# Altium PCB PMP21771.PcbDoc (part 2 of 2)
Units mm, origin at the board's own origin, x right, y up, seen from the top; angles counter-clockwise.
Board outline 125.73 x 87.63 mm, 4 copper layers (Top Layer, Signal Layer 1, Signal Layer 2, Bottom Layer), stack 2.225 mm thick; 58 components, 23 nets, 122 pads, 58 vias.
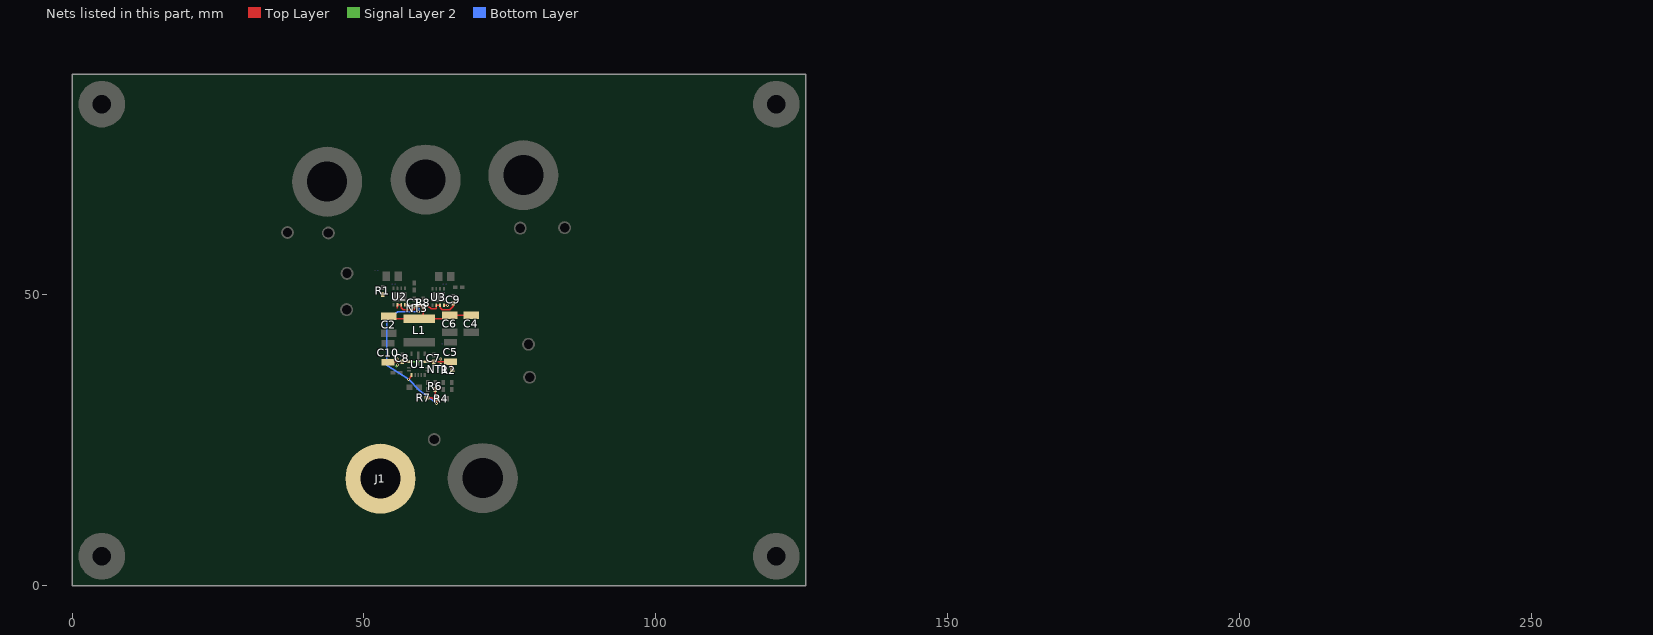
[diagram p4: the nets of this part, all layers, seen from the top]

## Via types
v1: diameter 0.508, hole 0.203, Top Layer to Bottom Layer, 50 vias
v2: diameter 0.5, hole 0.2, Top Layer to Bottom Layer, 8 vias

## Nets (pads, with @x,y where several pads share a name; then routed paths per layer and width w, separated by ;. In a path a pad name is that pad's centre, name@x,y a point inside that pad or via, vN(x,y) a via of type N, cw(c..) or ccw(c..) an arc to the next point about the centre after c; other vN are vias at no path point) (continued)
VIN: C5.1 C7.1 C8.1 C10.1 J1.1 NT1.2 R2.2 U1.8 U1.12 | length 23
  Top Layer w0.254: J1.1@52.702,18.498 J1.1@52.825,18.375 ; C10.1@54.126,38.3 54.226,38.4 C8.1@56.576,38.4 57.821,38.4 U1.12@57.836,38.415 ; U1.8@61.135,38.415 U1.8@60.736,38.415 60.746,38.425 C5.1@64.826,38.425 ; R2.2@65.1,36.925 C5.1@64.826,38.425 ; C5.1@65.1,38.151 C5.1@64.826,38.425
  Signal Layer 2 w0.254: J1.1@52.825,18.375 J1.1@55.75,21.3 ; 55.439,37.572 v1(55.75,37.883) ; 55.825,38.4 63.175,38.4
  Bottom Layer w0.254: NT1.2@62.715,37.4 62.715,37.49 v1(63.15,37.925)
  other v1: 55.775,38.85 63.15,38.85
VIN2: C1.1 C2.1 C4.1 C6.1 C9.1 L1.2 NT3.1 R1.2 R4.2 R6.2 R7.2 R8.2 U1.1 U2.2 U2.3 U2.4 U3.2 U3.3 U3.4 | length 62.5
  Top Layer w0.254: R1.2@53.134,50.2 R1.2@53.23,50.104 ; C2.1@54.25,46.174 54.627,45.797 L1.2@59.476,45.797 ; 55.721,47.571 U2.2@55.721,48.171 U2.3@56.371,48.171 56.371,47.671 56.737,47.305 58.598,47.305 C1.1@58.598,47.955 R8.2@60.18,47.955 ; U2.4@57.021,48.171 v1(57.7,48.171) ; v1(57.65,35.4) 58.136,35.886 U1.1@58.136,36.115 ; R7.2@60.8,32.232 61.575,32.232 61.745,32.062 R4.2@62.443,32.062 ; R6.2@62.24,33.65 62.24,32.265 R4.2@62.443,32.062 ; v1(62.443,31.275) R4.2@62.443,32.062 ; U3.4@63.69,48.1 64.275,48.1 v1(64.3,48.075) ; C9.1@65.33,48.421 65.33,47.906 64.702,47.278 63.392,47.278 63.04,47.63 U3.3@63.04,48.1 U3.2@62.39,48.1 62.368,48.078 62.368,47.575 62.268,47.475 61.998,47.475 61.996,47.473 61.483,47.473 61.002,47.955 R8.2@60.18,47.955 ; C4.1@68.395,46.378 C6.1@64.702,46.378 64.121,45.797 L1.2@59.476,45.797 ; L1.2@59.476,45.797 60.18,46.501 R8.2@60.18,47.955
  Bottom Layer w0.254: NT3.1@59.4,47.575 59.4,47.025 v1(59.35,46.975) 55.79,46.975 55.752,47.012 53.86,45.71 53.86,37.765 v1(57.65,35.4) 59.485,33.565 v1(62.443,31.275)
pads on no net: H1.1 H2.1 H3.1 H4.1 H5.0 H6.0 H7.0 H8.0 U1.10@59.286,38.315 U1.10@59.286,39.615 U2.9@55.416,49.571 U2.9@56.676,49.571 U3.9@62.085,49.5 U3.9@63.345,49.5
copper on no net: | length 2642.9
  Signal Layer 1 w0.025: 236.74,55.732 239.272,58.264 242.32,61.312 245.368,64.36 248.416,67.408 251.464,70.456 254.512,73.504 257.56,76.552 260.608,79.6 263.656,82.648 265.18,84.172 ; 236.74,57.256 237.748,58.264 240.796,61.312 243.844,64.36 246.892,67.408 249.94,70.456 252.988,73.504 256.036,76.552 259.084,79.6 262.132,82.648 265.18,85.696 ; 236.74,58.78 239.272,61.312 242.32,64.36 245.368,67.408 248.416,70.456 251.464,73.504 254.512,76.552 257.56,79.6 260.608,82.648 263.656,85.696 265.18,87.22 ; 236.74,60.304 237.748,61.312 240.796,64.36 243.844,67.408 246.892,70.456 249.94,73.504 252.988,76.552 256.036,79.6 259.084,82.648 262.132,85.696 265.18,88.744 ; 236.74,61.828 239.272,64.36 242.32,67.408 245.368,70.456 248.416,73.504 251.464,76.552 254.512,79.6 257.56,82.648 260.608,85.696 263.656,88.744 ; 236.74,63.352 237.748,64.36 240.796,67.408 243.844,70.456 246.892,73.504 249.94,76.552 252.988,79.6 256.036,82.648 259.084,85.696 262.132,88.744 ; 236.74,64.876 239.272,67.408 242.32,70.456 245.368,73.504 248.416,76.552 251.464,79.6 254.512,82.648 257.56,85.696 260.608,88.744 ; 236.74,66.4 237.748,67.408 240.796,70.456 243.844,73.504 246.892,76.552 249.94,79.6 252.988,82.648 256.036,85.696 259.084,88.744 ; 236.74,67.924 239.272,70.456 242.32,73.504 245.368,76.552 248.416,79.6 251.464,82.648 254.512,85.696 257.56,88.744 ; 236.74,69.448 237.748,70.456 240.796,73.504 243.844,76.552 246.892,79.6 249.94,82.648 252.988,85.696 256.036,88.744 ; 236.74,70.972 239.272,73.504 242.32,76.552 245.368,79.6 248.416,82.648 251.464,85.696 254.512,88.744 ; 236.74,72.496 237.748,73.504 240.796,76.552 243.844,79.6 246.892,82.648 249.94,85.696 252.988,88.744 ; 236.74,74.02 239.272,76.552 242.32,79.6 245.368,82.648 248.416,85.696 251.464,88.744 ; 236.74,75.544 237.748,76.552 240.796,79.6 243.844,82.648 246.892,85.696 249.94,88.744 ; 236.74,77.068 239.272,79.6 242.32,82.648 245.368,85.696 248.416,88.744 ; 236.74,78.592 237.748,79.6 240.796,82.648 243.844,85.696 246.892,88.744 ; 236.74,80.116 239.272,82.648 242.32,85.696 245.368,88.744 ; 236.74,81.64 237.748,82.648 240.796,85.696 243.844,88.744 ; 236.74,83.164 239.272,85.696 242.32,88.744 ; 236.74,84.688 237.748,85.696 240.796,88.744 ; 236.74,86.212 239.272,88.744 ; 236.74,87.736 237.748,88.744 ; 237.748,55.216 240.796,58.264 243.844,61.312 246.892,64.36 249.94,67.408 252.988,70.456 256.036,73.504 259.084,76.552 262.132,79.6 265.18,82.648 ; 239.272,55.216 242.32,58.264 245.368,61.312 248.416,64.36 251.464,67.408 254.512,70.456 257.56,73.504 260.608,76.552 263.656,79.6 265.18,81.124 ; 240.796,55.216 243.844,58.264 246.892,61.312 249.94,64.36 252.988,67.408 256.036,70.456 259.084,73.504 262.132,76.552 265.18,79.6 ; 242.32,55.216 245.368,58.264 248.416,61.312 251.464,64.36 254.512,67.408 257.56,70.456 260.608,73.504 263.656,76.552 265.18,78.076 ; 243.844,55.216 246.892,58.264 249.94,61.312 252.988,64.36 256.036,67.408 259.084,70.456 262.132,73.504 265.18,76.552 ; 245.368,55.216 248.416,58.264 251.464,61.312 254.512,64.36 257.56,67.408 260.608,70.456 263.656,73.504 265.18,75.028 ; 246.892,55.216 249.94,58.264 252.988,61.312 256.036,64.36 259.084,67.408 262.132,70.456 265.18,73.504 ; 248.416,55.216 251.464,58.264 254.512,61.312 257.56,64.36 260.608,67.408 263.656,70.456 265.18,71.98 ; 249.94,55.216 252.988,58.264 256.036,61.312 259.084,64.36 262.132,67.408 265.18,70.456 ; 251.464,55.216 254.512,58.264 257.56,61.312 260.608,64.36 263.656,67.408 265.18,68.932 ; 252.988,55.216 256.036,58.264 259.084,61.312 262.132,64.36 265.18,67.408 ; 254.512,55.216 257.56,58.264 260.608,61.312 263.656,64.36 265.18,65.884 ; 256.036,55.216 259.084,58.264 262.132,61.312 265.18,64.36 ; 257.56,55.216 260.608,58.264 263.656,61.312 265.18,62.836 ; 259.084,55.216 262.132,58.264 265.18,61.312 ; 260.608,55.216 263.656,58.264 265.18,59.788 ; 262.132,55.216 265.18,58.264 ; 263.656,55.216 265.18,56.74
  Signal Layer 1 w0.381: 149.641,58.264 160.052,58.264 183.922,58.264 205.76,58.264 222.266,58.264 236.74,58.264 265.18,58.264 ; 149.641,61.312 160.052,61.312 183.922,61.312 205.76,61.312 222.266,61.312 236.74,61.312 265.18,61.312 ; 149.641,64.36 160.052,64.36 183.922,64.36 205.76,64.36 222.266,64.36 236.74,64.36 265.18,64.36 ; 149.641,67.408 160.052,67.408 183.922,67.408 205.76,67.408 222.266,67.408 236.74,67.408 265.18,67.408 ; 149.641,70.456 160.052,70.456 183.922,70.456 205.76,70.456 222.266,70.456 236.74,70.456 265.18,70.456 ; 149.641,73.504 160.052,73.504 183.922,73.504 205.76,73.504 222.266,73.504 236.74,73.504 265.18,73.504 ; 149.641,76.552 160.052,76.552 183.922,76.552 205.76,76.552 222.266,76.552 236.74,76.552 265.18,76.552 ; 149.641,79.6 160.052,79.6 183.922,79.6 205.76,79.6 222.266,79.6 236.74,79.6 265.18,79.6 ; 149.641,82.648 160.052,82.648 183.922,82.648 205.76,82.648 222.266,82.648 236.74,82.648 265.18,82.648 ; 149.641,85.696 160.052,85.696 183.922,85.696 205.76,85.696 222.266,85.696 236.74,85.696 265.18,85.696 ; 149.641,88.744 265.18,88.744 ; 160.052,91.792 160.052,55.216 ; 183.922,91.792 183.922,55.216 ; 205.76,91.792 205.76,55.216 ; 222.266,91.792 222.266,55.216 ; 236.74,91.792 236.74,55.216 ; 160.052,55.216 149.641,55.216 149.641,91.792 265.18,91.792 265.18,55.216 236.74,55.216 ; 160.052,55.216 183.922,55.216 ; 183.922,55.216 205.76,55.216 ; 205.76,55.216 222.266,55.216 ; 222.266,55.216 236.74,55.216

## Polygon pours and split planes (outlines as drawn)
GND on Signal Layer 1 "SIGNAL_LAYER_1_GND_P152" (solid, remove dead copper, pour order 152): 126.05,87.63 125.603,87.183 125.603,-0.127 0.127,-0.127 0,0 0.325,0.325 0.325,87.63
OUT2 on Top Layer "TOP_LAYER_OUT2_P144" (solid, remove dead copper, pour order 144): 69.856,77.925 83.15,77.925 89.717,71.358 64.74,46.38 61.585,51.418
OUT1 on Top Layer "TOP_LAYER_OUT1_P145" (solid, remove dead copper, pour order 145): 36.526,76.525 47.573,76.525 55.082,63.955 56.791,50.994 50.514,50.661 35.977,65.198
GND on Top Layer "TOP_LAYER_GND_P150" (solid, remove dead copper, pour order 150): -0.713,87.783 125.312,87.783 125.312,0.194 125.017,-0.101 124.763,0.153 -0.713,0.153
VIN on Top Layer "TOP_LAYER_VIN_P149" (solid, remove dead copper, pour order 149): 60.236,39.125 60.35,39.24 66.226,39.24 66.226,36.474 60.259,36.474
VIN on Top Layer "TOP_LAYER_VIN_P147" (solid, remove dead copper, pour order 147): 52.726,39.115 58.5,39.115 58.5,37.4 52.726,37.4
GND on Top Layer "TOP_LAYER_GND_P146" (solid, remove dead copper, pour order 146): 64.1,54 67.1,54 67.1,52.05 67.125,52.025 64.075,52.025
OUT2 on Top Layer "TOP_LAYER_OUT2_P143" (solid, remove dead copper, pour order 143): 61.996,54 63.589,54 63.589,50.483 63.575,50.469 63.544,50.5 61.986,50.5
OUT1 on Top Layer "TOP_LAYER_OUT1_P142" (solid, remove dead copper, pour order 142): 54.975,54.225 55.025,54.275 56.725,54.275 56.725,50.6 56.65,50.525 56.6,50.575 54.996,50.575
SW on Top Layer "TOP_LAYER_SW_P141" (solid, remove dead copper, pour order 141): 56.55,42.65 62.4,42.65 62.289,40.675 59.85,40.648 59.85,37.6 58.95,37.6 58.8,37.75 58.8,40.325 58.45,40.675 56.55,40.675
VIN2 on Top Layer "TOP_LAYER_VIN2_P140" (solid, remove dead copper, pour order 140): 51.7,50.85 51.85,51 70.275,51 70.275,44.75 51.7,44.75
VIN on Signal Layer 2 "SIGNAL_LAYER_2_VIN_P151" (solid, remove dead copper, pour order 151): 53.25,37.977 45.025,29.752 45.025,11.425 60.269,11.425 60.269,37.814
GND on Signal Layer 2 "SIGNAL_LAYER_2_GND_P153" (solid, remove dead copper, pour order 153): 0,87.63 125.156,87.63 125.603,87.183 125.25,86.83 125.25,0 0.1,0
VIN on Signal Layer 2 "SIGNAL_LAYER_2_VIN_P148" (solid, remove dead copper, pour order 148): 52.561,39.115 52.786,39.34 66.486,39.34 66.486,36.225 66.461,36.2 66.421,36.24 64.082,36.24 64.082,36.499 63.292,37.29 63.217,37.215 52.561,37.215
GND on Bottom Layer "BOTTOM_LAYER_GND_P154" (solid, remove dead copper, pour order 154): 0,87.35 0.167,87.183 125.603,87.183 125.603,0.447 126.05,0 0.15,0

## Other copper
Signal Layer 1:
  text "Layer" at 151.165,89.506 h1.52
  text "Name" at 161.576,89.506 h1.52
  text "Material" at 185.446,89.506 h1.52
  text "Thickness" at 207.284,89.506 h1.52
  text "Constant" at 223.79,89.506 h1.52
  text "Board Layer Stack" at 238.264,89.506 h1.52
  text "1" at 151.165,86.458 h1.52
  text "Top Overlay" at 161.576,86.458 h1.52
  text "2" at 151.165,83.41 h1.52
  text "Top Solder" at 161.576,83.41 h1.52
  text "Solder Resist" at 185.446,83.41 h1.52
  text "0.40mil" at 207.284,83.41 h1.52
  text "3.5" at 223.79,83.41 h1.52
  text "3" at 151.165,80.362 h1.52
  text "Top Layer" at 161.576,80.362 h1.52
  text "Copper" at 185.446,80.362 h1.52
  text "2.80mil" at 207.284,80.362 h1.52
  text "4" at 151.165,77.314 h1.52
  text "Dielectric 2" at 161.576,77.314 h1.52
  text "10.00mil" at 207.284,77.314 h1.52
  text "4.2" at 223.79,77.314 h1.52
  text "5" at 151.165,74.266 h1.52
  text "Signal Layer 1" at 161.576,74.266 h1.52
  text "Copper" at 185.446,74.266 h1.52
  text "1.40mil" at 207.284,74.266 h1.52
  text "6" at 151.165,71.218 h1.52
  text "Dielectric1" at 161.576,71.218 h1.52
  text "FR-4" at 185.446,71.218 h1.52
  text "59.20mil" at 207.284,71.218 h1.52
  text "4.8" at 223.79,71.218 h1.52
  text "7" at 151.165,68.17 h1.52
  text "Signal Layer 2" at 161.576,68.17 h1.52
  text "Copper" at 185.446,68.17 h1.52
  text "1.40mil" at 207.284,68.17 h1.52
  text "8" at 151.165,65.122 h1.52
  text "Dielectric 3" at 161.576,65.122 h1.52
  text "10.00mil" at 207.284,65.122 h1.52
  text "4.2" at 223.79,65.122 h1.52
  text "9" at 151.165,62.074 h1.52
  text "Bottom Layer" at 161.576,62.074 h1.52
  text "Copper" at 185.446,62.074 h1.52
  text "2.80mil" at 207.284,62.074 h1.52
  text "10" at 151.165,59.026 h1.52
  text "Bottom Solder" at 161.576,59.026 h1.52
  text "Solder Resist" at 185.446,59.026 h1.52
  text "0.40mil" at 207.284,59.026 h1.52
  text "3.5" at 223.79,59.026 h1.52
  text "11" at 151.165,55.978 h1.52
  text "Bottom Overlay" at 161.576,55.978 h1.52

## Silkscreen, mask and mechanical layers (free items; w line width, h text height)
Top Overlay:
  lines w0.1: 51.1,30.6 51.1,36.625 51.1,48.675 51.1,54.7 70.825,54.7 70.775,30.6 51.1,30.6
M1 Board Outline:
  lines w0.254: 0,0 0,87.63 136.5,87.63 136.5,0 0,0
M2 Board Dimensions:
  rectangle: 0,-6.985 3.175,-3.81
  rectangle: 3.175,-10.16 12.7,-6.985
  lines w0.178: 0,-6.985 25.4,-6.985 ; 3.175,-10.16 3.175,-3.81 ; 6.35,-10.16 6.35,-3.81 ; 12.7,-10.16 12.7,-3.81 ; 19.05,-10.16 19.05,-3.81 ; 0,-10.16 25.4,-10.16 25.4,-3.81 0,-3.81 0,-10.16
M5 Assembly Top:
  lines w0.254: -7.417,-23.626 160.223,-23.626 ; -7.417,-18.462 160.274,-18.462 ; -7.417,-13.297 -7.417,-28.791 94.31,-28.791 160.274,-28.791 160.274,-13.297 -7.404,-13.297 -7.404,-28.791 32.614,-28.791 ; 55.194,-28.791 55.194,-13.297 ; 87.376,-18.462 87.376,-13.297 ; 108.712,-18.462 108.712,-13.297 ; 124.511,-28.956 124.511,-23.804
  text "REV:" at 92.405,-16.654 h1.52
  text ".PCB_Rev" at 99.809,-16.654 h1.52
  text "SVN REV:" at 113.69,-16.654 h1.52
  text ".VersionControl_RevNumber" at 126.543,-16.654 h1.52
  text "TID #:" at 57.099,-21.819 h1.52
  text ".TID" at 70.955,-21.819 h1.52
  text "PLOT NAME =" at -5.804,-27.034 h1.52
  text ".Print_Date" at 79.235,-27.034 h1.52
  text "TEXAS INSTRUMENTS" at 129.87,-27.034 h1.52
M6 Assembly Bottom:
  lines w0.254: -7.429,-18.474 160.261,-18.474 ; -7.379,-23.639 160.261,-23.639 ; 28.334,-28.969 28.334,-23.817 ; 44.133,-18.474 44.133,-13.31 ; 65.468,-18.474 65.468,-13.31 ; 97.65,-28.804 97.65,-13.31 ; 120.231,-28.804 160.249,-28.804 160.249,-13.31 -7.429,-13.31 -7.429,-28.804 58.534,-28.804 160.261,-28.804 160.261,-13.31
  text ".VersionControl_RevNumber" at 26.302,-16.667 h1.52
M9 Title Sheet:
  drawing of 57 lines, arcs and shapes, not listed
  text "1" at 18.792,204.127 h1.78
  text "2" at 82.182,204.127 h1.78
  text "3" at 145.411,204.127 h1.78
  text "4" at 209.08,204.127 h1.78
  text "5" at 272.555,204.127 h1.78
  text "6" at 336.182,204.127 h1.78
  text "A" at -10.579,175.095 h1.78
  text "A" at 365.341,175.095 h1.78
  text "B" at -10.579,114.643 h1.78
  text "B" at 365.341,114.643 h1.78
  text "C" at -10.579,54.318 h1.78
  text "C" at 365.341,54.318 h1.78
  text "PROJECT TITLE:" at 288.125,7.048 h1.14
  text "Dual Type-C Charge Port" at 289.395,3.662 h1.78
  text "DESIGNED FOR:" at 288.125,-0.597 h1.14
  text "Aptiv" at 289.395,-4.153 h1.78
  text "D" at 365.341,-5.88 h1.78
  text "FILE NAME:" at 288.125,-8.217 h1.14
  text ".PCB_File_Name_No_Path" at 289.395,-11.265 h1.78
  text "Texas Instruments (TI) and/or its licensors do not warrant the accuracy or completeness of this specification" at 161.9,-15.376 h1.14
  text "ENGINEER:" at 288.125,-15.583 h1.14
  text "LAYOUT BY:" at 326.352,-15.583 h1.14
  text "or any information contained therein. TI and/or its licensors do not warrant that this design will meet" at 160.757,-18.237 h1.14
  text "PMP21771" at 289.395,-19.52 h1.78
  text "Sahana Krishnan" at 327.635,-19.52 h1.78
  text "the specifications, will be suitable for your application or fit for any particular purpose, or will operate in" at 160.757,-21.099 h1.14
  text "ALTIUM DESIGNER VERSION:" at 326.352,-23.457 h1.14
  text "an implementation. TI and/or its licensors do not warrant that the design is production worthy. You should" at 160.757,-23.961 h1.14
  text "completely validate and test your design implementation to confirm the system functionality for your application." at 161.9,-26.822 h1.14
  text ".print_Scale" at 289.395,-26.843 h1.78
  text ".Application_BuildNumber" at 327.635,-26.843 h1.78
  text "1" at 18.792,-32.093 h1.78
  text "2" at 82.182,-32.093 h1.78
  text "3" at 145.411,-32.093 h1.78
  text "4" at 209.08,-32.093 h1.78
  text "5" at 272.555,-32.093 h1.78
  text "6" at 336.182,-32.093 h1.78
M10 Fab Notes:
  drawing of 189 lines, arcs and shapes, not listed
  text "DESIGN INFORMATION" at 314.503,161.447 h1.52
  text "MIN. TRACK WIDTH:" at 298.131,158.091 h1.52
  text "8" at 325.976,158.091 h1.52
  text "MIL" at 329.907,158.091 h1.52
  text "MIN. CLEARANCE:" at 298.131,154.938 h1.52
  text "0.2" at 324.452,154.938 h1.52
  text "mm" at 329.907,154.938 h1.52
  text "MIN. VIA PAD SIZE:" at 298.131,151.785 h1.52
  text "24" at 325.214,151.785 h1.52
  text "MIL" at 329.907,151.785 h1.52
  text "0.05mm (2MIL)" at 315.784,148.486 h1.52
  text "MINIMUM ANNULAR RING" at 289.769,148.277 h1.52
  text "EXTERNAL" at 333.768,148.277 h1.52
  text "PER" at 294.849,145.48 h1.52
  text "IPC-D-275 CLASS 2 LEVEL C" at 300.437,145.48 h1.52
  text "MIL, HOLES" at 338.238,142.928 h1.52
  text "+/-" at 328.27,142.709 h1.52
  text "+/-" at 349.961,142.709 h1.52
  text "REGISTRATION TOLERANCES:" at 289.769,142.682 h1.52
  text "METAL" at 320.243,142.682 h1.52
  text "5" at 334.879,142.683 h1.52
  text "3" at 356.037,142.683 h1.52
  text "MIL" at 358.99,142.682 h1.52
  text "HOLE SIZE TOLERANCE (UNLESS OTHERWISE SPECIFIED):" at 289.769,140.185 h1.52
  text "+/-" at 349.961,140.112 h1.52
  text "3" at 356.037,140.085 h1.52
  text "MIL" at 358.99,140.085 h1.52
  text "MATERIAL:" at 287.87,136.589 h1.52
  text "FR-4 High Tg" at 312.926,133.324 h1.52
  text "X" at 309.257,133.122 h1.52
  text "FR-408" at 298.563,133.007 h1.52
  text "OTHER" at 336.358,133.007 h1.52
  text "62 MIL (1.6mm) +/-10%" at 306.694,129.374 h1.52
  text "X" at 303.643,129.312 h1.52
  text "THICKNESS:" at 289.769,129.165 h1.52
  text "OTHER" at 339.33,129.165 h1.52
  text "TOLERANCE:" at 289.769,125.652 h1.52
  text "X" at 311.314,125.652 h1.52
  text "ANSI IPC-6012 TYPE 3 CLASS 2" at 315.836,125.652 h1.52
  text "OTHER +/-" at 315.835,121.989 h1.52
  text "BOW & TWIST:" at 289.769,118.302 h1.52
  text "X" at 311.314,118.302 h1.52
  text "ANSI IPC-6012 TYPE 3 CLASS 2" at 315.836,118.302 h1.52
  text "OTHER +/-" at 315.835,114.576 h1.52
  text "DRILLING:" at 287.87,111.258 h1.52
  text "NC_DRILL FILES" at 332.599,108.586 h1.52
  text "REFERENCE:" at 289.769,108.486 h1.52
  text "X" at 306.463,108.484 h1.52
  text "AS SHOWN" at 310.984,108.486 h1.52
  text "X" at 329.348,108.486 h1.52
  text "OTHER" at 340.168,104.873 h1.52
  text "PTH COPPER THICKNESS:" at 289.761,104.783 h1.52
  text "X" at 318.697,104.783 h1.52
  text "20-30 um" at 321.948,104.783 h1.52
  text "BOARD FINISH:" at 287.87,101.034 h1.52
  text "SILKSCREEN:" at 291.812,98.237 h1.52
  text "X" at 316.14,98.237 h1.52
  text "TOP" at 319.112,98.237 h1.52
  text "X" at 329.094,98.237 h1.52
  text "BOTTOM" at 332.091,98.237 h1.52
  text "SILKSCREEN COLOR:" at 291.812,94.295 h1.52
  text "X" at 316.115,94.295 h1.52
  text "WHITE" at 319.112,94.295 h1.52
  text "OTHER" at 332.091,94.295 h1.52
  text "X" at 319.442,90.652 h1.52
  text "GREEN" at 322.439,90.652 h1.52
  text "OTHER" at 338.136,90.652 h1.52
  text "SOLDER RESIST COLOR:" at 291.812,90.477 h1.52
  text "X" at 319.442,86.734 h1.52
  text "MATTE" at 322.439,86.734 h1.52
  text "SEMI-GLOSS" at 338.125,86.717 h1.52
  text "IMMERSION GOLD (ENIG)" at 314.819,82.345 h1.52
  text "ENEPIG" at 348.793,82.162 h1.52
  text "SURFACE FINISH:" at 287.87,82.136 h1.52
  text "X" at 310.298,82.136 h1.52
  text "IMM. TIN/SILVER OR EQUIV" at 296.24,78.649 h1.52
  text "OTHER" at 332.599,78.549 h1.52
  text "ARRAY/PANEL:" at 287.87,74.602 h1.52
  text "CUT AND TRIM PER M1 BOARD OUTLINE" at 314.819,74.393 h1.52
  text "N.C. ROUTE" at 314.819,70.94 h1.52
  text "X" at 332.295,70.94 h1.52
  text "V. SCORE" at 336.816,70.94 h1.52
  text "CERTIFICATION:" at 287.87,67.66 h1.52
  text "MATERIALS AND WORKMANSHIP FOR ALL PCBS" at 306.285,67.66 h1.52
  text "TO MEET OR EXCEED THE REQUIREMENTS OF:" at 306.285,65.271 h1.52
  text "X" at 297.078,62.003 h1.52
  text "ANSI IPC-A-600F CLASS ->" at 300.329,62.003 h1.52
  text "X" at 342.188,62.003 h1.52
  text "2" at 344.982,62.003 h1.52
  text "1" at 336.981,61.965 h1.52
  text "3" at 353.973,61.965 h1.52
  text "X" at 317.702,58.252 h1.52
  text "RoHS" at 320.953,58.252 h1.52
  text "OTHER" at 337.321,58.252 h1.52
  text "PER ORDER" at 347.407,58.252 h1.52
  text "ALL BOARDS MUST MEET OR EXCEED UL94-V0 REQUIREMENTS." at 288.569,54.345 h1.52
  text "PCB MUST BEAR THE UL94V-0 UL REGISTERED MATERIAL ID NUMBER" at 288.569,51.397 h1.52
  text "ADDITIONAL REQUIREMENTS:" at 287.87,47.094 h1.52
  text "MICROSECTION:" at 289.769,44.373 h1.52
  text "YES" at 312.775,44.373 h1.52
  text "REQUIRED" at 334.657,40.707 h1.52
  text "BARE BOARD ELEC. TEST:" at 289.769,40.634 h1.52
  text "NONE" at 322.935,40.634 h1.52
  text "X" at 331.66,40.634 h1.52
  text "PER ORDER" at 349.693,40.634 h1.52
  text "XX MIL VIAS REQUIRE NON-CONDUCTIVE FILL AND PLANARIZE" at 294.04,35.428 h1.5
  text "XX MIL VIAS REQUIRE CONDUCTIVE FILL AND PLANARIZE" at 294.243,32.787 h1.52
  text "OUTER XX MIL TRACES REQUIRE 50 OHM SINGLE-ENDED IMPEDANCE" at 294.218,28.637 h1.47
  text "LAYER 2 & 3 (INNER LAYERS) XX MIL WIDE, XX MIL SPACE / TRACES REQUIRE 100 OHM DIFFERENTIAL IMPEDANCE" at 294.015,22.65 h1.52
M11 Gerber Information:
  lines w0.254: -7.417,-23.626 160.223,-23.626 ; -7.417,-18.462 160.274,-18.462 ; -7.417,-13.297 -7.417,-28.791 94.31,-28.791 160.274,-28.791 160.274,-13.297 -7.404,-13.297 -7.404,-28.791 32.614,-28.791 ; 55.194,-28.791 55.194,-13.297 ; 87.376,-18.462 87.376,-13.297 ; 108.712,-18.462 108.712,-13.297 ; 124.511,-28.956 124.511,-23.804
  text "BOARD #:" at 57.099,-16.654 h1.52
  text "PMP21771" at 70.955,-16.654 h1.52
  text "REV:" at 92.405,-16.654 h1.52
  text ".PCB_Rev" at 99.809,-16.654 h1.52
  text "SVN REV:" at 113.69,-16.654 h1.52
  text ".VersionControl_RevNumber" at 126.543,-16.654 h1.52
  text "LAYER NAME =" at -5.804,-21.806 h1.52
  text "TID #:" at 57.099,-21.819 h1.52
  text ".TID" at 70.955,-21.819 h1.52
  text "PLOT NAME =" at -5.804,-27.034 h1.52
  text "GENERATED    :" at 57.15,-27.034 h1.52
  text ".Print_Date" at 79.235,-27.034 h1.52
  text ".Print_Time" at 97.752,-27.034 h1.52
  text "TEXAS INSTRUMENTS" at 129.87,-27.034 h1.52
Drill Drawing:
  circle w0.254: c161.226,33.627 r0.702
  lines w0.254: 160.525,30.119 160.876,30.119 161.226,29.768 161.577,30.119 161.928,30.119 161.577,30.469 161.928,30.82 161.577,30.82 161.226,31.171 160.876,30.82 160.525,30.82 160.876,30.469 160.525,30.119 ; 160.525,36.083 161.226,36.434 161.928,36.083 161.577,36.785 161.928,37.487 161.226,37.136 160.525,37.487 160.876,36.785 160.525,36.083 ; 160.525,40.644 161.928,40.644 161.226,39.241 160.525,40.644 ; 160.525,42.399 161.928,42.399 161.928,43.802 160.525,43.802 160.525,42.399
  lines w0.305: 159.252,28.82 241.332,28.82 ; 159.252,44.609 241.332,44.609 ; 167.834,25.663 167.834,47.767 ; 176.267,25.663 176.267,47.767 ; 192.436,25.663 192.436,47.767 ; 199.018,25.663 199.018,47.767 ; 208.547,25.663 208.547,47.767 ; 226.945,25.663 226.945,47.767 ; 159.252,25.663 241.332,25.663 241.332,47.767 159.252,47.767 159.252,25.663
  text "Symbol" at 161.147,45.556 h1.83
  text "Quantity" at 168.781,45.556 h1.83
  text "Finished Hole Size" at 177.214,45.556 h1.83
  text "Plated" at 193.383,45.556 h1.83
  text "Hole Type" at 199.965,45.556 h1.83
  text "Drill Layer Pair" at 209.494,45.556 h1.83
  text "Hole Tolerance" at 227.892,45.556 h1.83
  text "8" at 168.781,42.399 h1.52
  text "0.200mm (7.87mil)" at 177.214,42.399 h1.52
  text "PTH" at 193.383,42.399 h1.52
  text "Round" at 199.965,42.399 h1.52
  text "Top Layer - Bottom Layer" at 209.494,42.399 h1.52
  text "50" at 168.781,39.241 h1.52
  text "0.203mm (8.00mil)" at 177.214,39.241 h1.52
  text "PTH" at 193.383,39.241 h1.52
  text "Round" at 199.965,39.241 h1.52
  text "Top Layer - Bottom Layer" at 209.494,39.241 h1.52
  text "9" at 168.781,36.083 h1.52
  text "1.600mm (63.00mil)" at 177.214,36.083 h1.52
  text "PTH" at 193.383,36.083 h1.52
  text "Round" at 199.965,36.083 h1.52
  text "Top Layer - Bottom Layer" at 209.494,36.083 h1.52
  text "4" at 168.781,32.925 h1.52
  text "3.200mm (125.98mil)" at 177.214,32.925 h1.52
  text "PTH" at 193.383,32.925 h1.52
  text "Round" at 199.965,32.925 h1.52
  text "Top Layer - Bottom Layer" at 209.494,32.925 h1.52
  text "5" at 168.781,29.768 h1.52
  text "6.858mm (270.00mil)" at 177.214,29.768 h1.52
  text "PTH" at 193.383,29.768 h1.52
  text "Round" at 199.965,29.768 h1.52
  text "Top Layer - Bottom Layer" at 209.494,29.768 h1.52
  text "76 Total" at 168.781,26.61 h1.52
M17 Embedded Cavity:
  text ".Layer_Name" at 14.656,-21.806 h1.52
M18 Embedded Assembly:
  text ".Layer_Name" at 14.656,-21.806 h1.52
M19 Embedded Keepout:
  text ".Layer_Name" at 14.656,-21.806 h1.52

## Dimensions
70.775,30.6 to 70.825,54.7 on Top Overlay
51.1,54.7 to 70.825,54.7 on Top Overlay
0,-10.16 to 25.4,-10.16 on M2 Board Dimensions
0,0 to 0,87.63 on M2 Board Dimensions
0,0 to 125.73,0 on M2 Board Dimensions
